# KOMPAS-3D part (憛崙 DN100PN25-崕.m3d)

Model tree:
1. Объединить компоненты:1  (labels: СЕНС DN100PN25-НО)

Referenced files in D:\Савин\!СЕНСОР\3D для заказчика\!Новый перечень\СЕНС\2. СЕНС-НО\DN100\: СЕНС DN100PN25-НО.a3d
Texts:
  СЕНС DN100PN25-НО
  ООО НПП Сенсор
